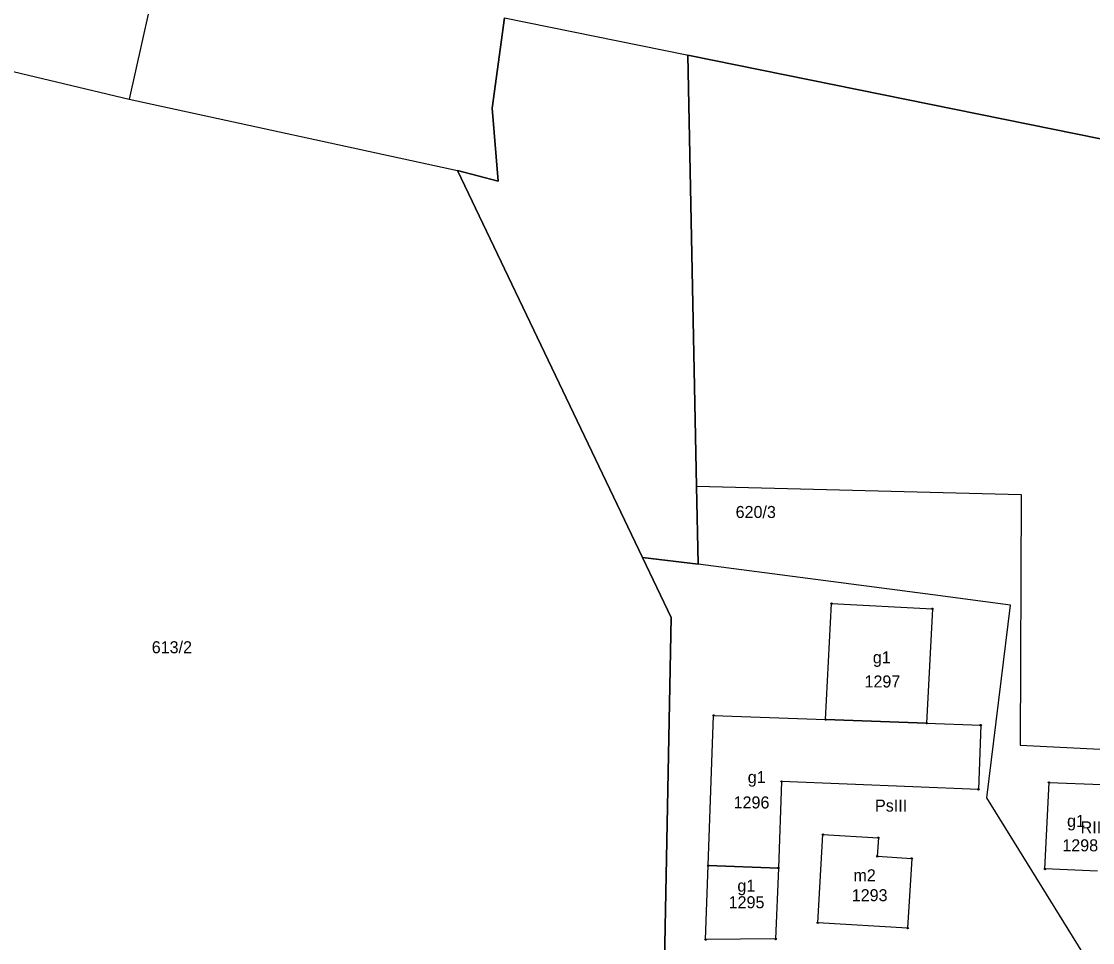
# Model space of a CAD drawing. Extents: x 7498273 to 7499989, y 5499795 to 5500810.
# Drawn here: x 7498760.3 to 7498893.9, y 5500550.6 to 5500665.5 of the extents above; entities that cross this region are included whole.
import ezdxf

# ---------------------------------------------------------------- set-up
doc = ezdxf.new("R2010")
doc.units = 0
for name, color, linetype in [('209-oznaczenie konturu klasyfikacyjnego', 7, 'Continuous'), ('211-numer działki ewidencyjnej', 7, 'Continuous'), ('217-kontur klasyfikacyjny', 7, 'Continuous'), ('218-kontur użytku gruntowego', 7, 'Continuous'), ('219-działka ewidencyjna', 7, 'Continuous'), ('312-budynek ewidencyjny', 7, 'Continuous'), ('312-oznaczenie budynku ewidencyjnego', 7, 'Continuous'), ('312-oznaczenie budynku ewidencyjnego-Atr117', 7, 'Continuous'), ('Punkt budynku', 7, 'Continuous')]:
    doc.layers.add(name, color=color, linetype=linetype)

# ---------------------------------------------------------------- blocks, each defined once
blk = doc.blocks.new('PUNKTBUD')
blk.add_circle((0, 0), 0.09)

msp = doc.modelspace()

# ---------------------------------------------------------------- linework, layer by layer
at = {"layer": '217-kontur klasyfikacyjny'}
for points in [[(7498820.57, 5500665.94), (7498819.02, 5500654.66)], [(7498735, 5500665.04), (7498773.75, 5500655.79)], [(7498844.51, 5500607.5), (7498843.43, 5500661.3)], [(7498843.43, 5500661.3), (7498919.07, 5500645.93)], [(7498773.75, 5500655.79), (7498814.69, 5500646.9)], [(7498819.02, 5500654.66), (7498819.76, 5500645.58)], [(7498819.76, 5500645.58), (7498814.69, 5500646.9)], [(7498814.69, 5500646.9), (7498837.77, 5500598.63)], [(7498844.7, 5500597.8), (7498844.51, 5500607.5)], [(7498844.51, 5500607.5), (7498884.97, 5500606.49)], [(7498884.97, 5500606.49), (7498884.84, 5500575.23)], [(7498837.77, 5500598.63), (7498844.7, 5500597.8)], [(7498841.35, 5500591.13), (7498837.77, 5500598.63)], [(7498873.97, 5500593.96), (7498844.7, 5500597.8)], [(7498883.67, 5500592.69), (7498873.97, 5500593.96)], [(7498880.69, 5500568.66), (7498883.67, 5500592.69)], [(7498840.2, 5500533.22), (7498841.35, 5500591.13)], [(7498884.84, 5500575.23), (7498897.31, 5500574.57)], [(7498893.74, 5500547.57), (7498880.69, 5500568.66)]]:
    msp.add_lwpolyline(points, dxfattribs=at)
at = {"layer": '218-kontur użytku gruntowego'}
for points in [[(7498819.02, 5500654.66), (7498820.57, 5500665.94)], [(7498735, 5500665.04), (7498773.75, 5500655.79)], [(7498843.43, 5500661.3), (7498844.51, 5500607.5)], [(7498919.07, 5500645.93), (7498843.43, 5500661.3)], [(7498773.75, 5500655.79), (7498814.69, 5500646.9)], [(7498819.76, 5500645.58), (7498819.02, 5500654.66)], [(7498814.69, 5500646.9), (7498819.76, 5500645.58)], [(7498837.77, 5500598.63), (7498814.69, 5500646.9)], [(7498844.51, 5500607.5), (7498884.97, 5500606.49)], [(7498844.51, 5500607.5), (7498844.7, 5500597.8)], [(7498884.97, 5500606.49), (7498884.84, 5500575.23)], [(7498837.77, 5500598.63), (7498841.35, 5500591.13)], [(7498844.7, 5500597.8), (7498837.77, 5500598.63)], [(7498873.97, 5500593.96), (7498844.7, 5500597.8)], [(7498883.67, 5500592.69), (7498873.97, 5500593.96)], [(7498880.69, 5500568.66), (7498883.67, 5500592.69)], [(7498841.35, 5500591.13), (7498840.2, 5500533.22)], [(7498884.84, 5500575.23), (7498897.31, 5500574.57)], [(7498893.74, 5500547.57), (7498880.69, 5500568.66)]]:
    msp.add_lwpolyline(points, dxfattribs=at)
at = {"layer": '219-działka ewidencyjna'}
for points in [[(7498777.8, 5500673.87), (7498773.75, 5500655.79)], [(7498820.57, 5500665.94), (7498919.07, 5500645.93)], [(7498735, 5500665.04), (7498773.75, 5500655.79)], [(7498773.75, 5500655.79), (7498814.69, 5500646.9)], [(7498814.69, 5500646.9), (7498841.35, 5500591.13)], [(7498840.2, 5500533.22), (7498841.35, 5500591.13)]]:
    msp.add_lwpolyline(points, dxfattribs=at)
at = {"layer": '312-budynek ewidencyjny'}
for points in [[(7498860.6, 5500578.41), (7498861.35, 5500592.88)], [(7498861.35, 5500592.88), (7498873.91, 5500592.22)], [(7498873.91, 5500592.22), (7498873.2, 5500577.95)], [(7498845.96, 5500560.2), (7498846.64, 5500578.92)], [(7498846.64, 5500578.92), (7498860.6, 5500578.41)], [(7498860.6, 5500578.41), (7498873.2, 5500577.95)], [(7498873.2, 5500577.95), (7498860.6, 5500578.41)], [(7498873.2, 5500577.95), (7498879.95, 5500577.71)], [(7498879.95, 5500577.71), (7498879.66, 5500569.7)], [(7498855.12, 5500570.68), (7498854.71, 5500559.89)], [(7498879.66, 5500569.7), (7498855.12, 5500570.68)], [(7498887.95, 5500559.77), (7498888.46, 5500570.56)], [(7498888.46, 5500570.56), (7498895.01, 5500570.31)], [(7498859.61, 5500553.06), (7498860.26, 5500564.07)], [(7498860.26, 5500564.07), (7498867.18, 5500563.66)], [(7498867.18, 5500563.66), (7498867.04, 5500561.35)], [(7498867.04, 5500561.35), (7498871.34, 5500561.09)], [(7498871.34, 5500561.09), (7498870.83, 5500552.39)], [(7498845.63, 5500550.97), (7498845.96, 5500560.2)], [(7498845.96, 5500560.2), (7498854.71, 5500559.89)], [(7498854.71, 5500559.89), (7498845.96, 5500560.2)], [(7498854.71, 5500559.89), (7498854.37, 5500551.04)], [(7498894.52, 5500559.48), (7498887.95, 5500559.77)], [(7498870.83, 5500552.39), (7498859.61, 5500553.06)], [(7498854.37, 5500551.04), (7498845.63, 5500550.97)]]:
    msp.add_lwpolyline(points, dxfattribs=at)

# ---------------------------------------------------------------- block references
at = {"layer": 'Punkt budynku'}
for p in [(7498861.35, 5500592.88), (7498873.91, 5500592.22), (7498846.64, 5500578.92), (7498860.6, 5500578.41), (7498873.2, 5500577.95), (7498879.95, 5500577.71), (7498855.12, 5500570.68), (7498888.46, 5500570.56), (7498879.66, 5500569.7), (7498860.26, 5500564.07), (7498867.18, 5500563.66), (7498867.04, 5500561.35), (7498871.34, 5500561.09), (7498845.96, 5500560.2), (7498854.71, 5500559.89), (7498887.95, 5500559.77), (7498859.61, 5500553.06), (7498870.83, 5500552.39), (7498845.63, 5500550.97), (7498854.37, 5500551.04)]:
    msp.add_blockref('PUNKTBUD', p, dxfattribs=at)

# ---------------------------------------------------------------- texts
at = {"layer": '209-oznaczenie konturu klasyfikacyjnego'}
for s, p in [('PsIII', (7498866.76, 5500566.93)), ('RIIIb', (7498892.4, 5500564.2))]:
    msp.add_text(s, height=1.5, dxfattribs=at).set_placement(p)
at = {"layer": '211-numer działki ewidencyjnej'}
for s, p in [('620/3', (7498849.38, 5500603.55)), ('613/2', (7498776.57, 5500586.68))]:
    msp.add_text(s, height=1.5, dxfattribs=at).set_placement(p)
at = {"layer": '312-oznaczenie budynku ewidencyjnego'}
for s, p in [('1297', (7498865.45, 5500582.41)), ('1296', (7498849.13, 5500567.32)), ('1298', (7498890.12, 5500561.97)), ('1293', (7498863.86, 5500555.75)), ('1295', (7498848.51, 5500554.87))]:
    msp.add_text(s, height=1.5, dxfattribs=at).set_placement(p)
at = {"layer": '312-oznaczenie budynku ewidencyjnego-Atr117'}
for s, p in [('g1', (7498866.489, 5500585.42)), ('g1', (7498850.89, 5500570.48)), ('g1', (7498890.709, 5500565.02)), ('m2', (7498864.066, 5500558.23)), ('g1', (7498849.6, 5500556.94))]:
    msp.add_text(s, height=1.5, dxfattribs=at).set_placement(p)

doc.saveas('drawing.dxf')
